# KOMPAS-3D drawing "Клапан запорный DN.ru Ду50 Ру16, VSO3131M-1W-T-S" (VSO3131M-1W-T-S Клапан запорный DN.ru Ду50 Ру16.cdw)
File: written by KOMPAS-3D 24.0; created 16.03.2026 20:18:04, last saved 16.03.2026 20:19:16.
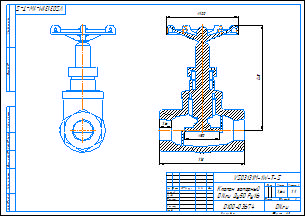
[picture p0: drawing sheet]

Document properties: c3d_UniqueCompID: 94d3474e-3e6e-4ddd-ad0b-ef51eb5e31da; Обозначение: VSO3131M-1W-T-S; Наименование: Клапан запорный DN.ru Ду32 Ру16; Материал: Сталь 10 ГОСТ 1050-2013; Автор: artiomk228874@gmail.com; Класс точности: c; Знак неуказанной шероховатости: Шероховатость не задана; Рассекать на разрезах: Да; Автор: artiomk228874@gmail.com; Форматы листов документа: A3; Полное имя файла: VSO3131M-1W-T-S Клапан запорный DN.ru Ду50 Ру16.m3d; Масса: 1.64; Наименование: Клапан запорный DN.ru Ду50 Ру16; Количество листов документа: 1; Примечание: D100-03674

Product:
- Body: Тело 1  | qty 1
    Масса: 2.2329
- Part/product: Клапан запорный DN.ru Ду50 Ру16  | designation VSO3131M-1W-T-S
    Масса: 1.64
    Раздел спецификации: Прочие изделия
    Форматы листов документа: A3
    Примечание: D100-03674
    additional columns: 94d3474e-3e6e-4ddd-ad0b-ef51eb5e31da; VSO3131M-1W-T-S; Клапан запорный DN.ru Ду32 Ру16; Сталь 10 ГОСТ 1050-2013; artiomk228874@gmail.com; c; Шероховатость не задана; Да

Referenced files in C:\Users\artio\OneDrive\Рабочий стол\Клапан запорный DN.ru VSO3131M-1W-T-S Ду15-Ду50 Ру16\Ду50\: VSO3131M-1W-T-S Клапан запорный DN.ru Ду50 Ру16.cdw, VSO3131M-1W-T-S Клапан запорный DN.ru Ду50 Ру16.m3d
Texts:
  Клапан запорный
  DN.ru Ду50 Ру16
  VSO3131M-1W-T-S
  Клапан запорный DN.ru Ду50 Ру16
  VSO3131M-1W-T-S Клапан запорный DN.ru Ду50 Ру16
Dimensions and other numbers on the sheet: 1:1; 0; 1; 2; 1,64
